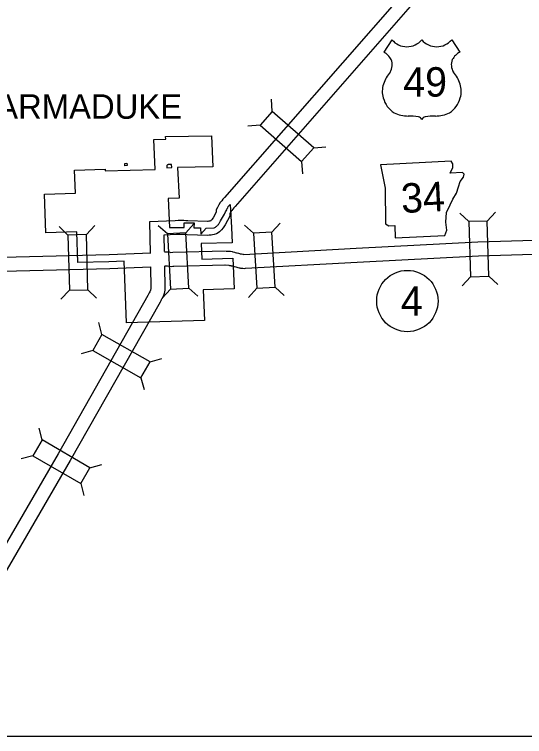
# Model space of a CAD drawing. Extents: x -0.3 to 2.65, y 0 to 1.9.
# Drawn here: x 0.1244 to 0.2273, y 0.5417 to 0.6874 of the extents above; entities that cross this region are included whole.
import ezdxf

# ---------------------------------------------------------------- set-up
doc = ezdxf.new("R2010")
doc.units = 0
for name, color, linetype in [('DSN_DRFT_DNC', 7, 'Continuous'), ('Level 21', 7, 'Continuous'), ('Level 22', 7, 'Continuous'), ('Level 26', 7, 'Continuous'), ('Level 27', 7, 'Continuous'), ('Level 38', 7, 'Continuous'), ('Level 59', 7, 'Continuous'), ('Level 6', 7, 'Continuous')]:
    doc.layers.add(name, color=color, linetype=linetype)

msp = doc.modelspace()

# ---------------------------------------------------------------- linework, layer by layer
at = {"layer": 'DSN_DRFT_DNC'}
msp.add_lwpolyline([(0.04166666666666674, 0.8750000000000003), (0.34166666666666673, 0.8750000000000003), (0.34166666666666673, 0.541666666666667), (0.04166666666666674, 0.541666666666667)], close=True, dxfattribs=at)
at = {"layer": 'Level 21'}
for points in [[(0.1670024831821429, 0.6396367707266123), (0.1679387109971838, 0.6395748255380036), (0.1683632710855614, 0.6395042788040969), (0.16837343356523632, 0.6395004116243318), (0.1687499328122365, 0.6393951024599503), (0.16893071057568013, 0.6393642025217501), (0.169170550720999, 0.6392932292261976), (0.16935035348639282, 0.6392487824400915), (0.16958915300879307, 0.6391819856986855), (0.16977474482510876, 0.6391246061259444), (0.16989319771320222, 0.6390960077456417), (0.1699938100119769, 0.639071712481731), (0.17021008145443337, 0.6390394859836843), (0.17044614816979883, 0.6389896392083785), (0.17054480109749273, 0.6389666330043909), (0.1706456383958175, 0.6389505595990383), (0.1706730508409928, 0.638947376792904), (0.1933438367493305, 0.6402108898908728), (0.21786572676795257, 0.6414539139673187), (0.22926085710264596, 0.6417985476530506)], [(0.15464540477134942, 0.6394811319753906), (0.15497090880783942, 0.6394587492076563), (0.1555985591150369, 0.6394402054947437), (0.15593432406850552, 0.6393627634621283), (0.1563514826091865, 0.6394126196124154), (0.16687934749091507, 0.6396395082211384)], [(0.09222026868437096, 0.6374214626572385), (0.09323654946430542, 0.6374956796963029), (0.09370798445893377, 0.6375075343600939), (0.0946621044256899, 0.6374841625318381), (0.0956582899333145, 0.637500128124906), (0.09666676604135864, 0.6375254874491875), (0.09792934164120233, 0.6375185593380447), (0.09863089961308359, 0.6375022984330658), (0.09898589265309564, 0.6375394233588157), (0.0994311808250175, 0.637529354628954), (0.10086031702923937, 0.637574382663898), (0.1060599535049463, 0.6378364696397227), (0.10886551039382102, 0.6379921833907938), (0.11137386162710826, 0.6380646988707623), (0.11226629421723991, 0.6381060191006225), (0.11516358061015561, 0.6381788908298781), (0.1185378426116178, 0.6382825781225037), (0.12474545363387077, 0.6384292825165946), (0.14352280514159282, 0.6389109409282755), (0.15190330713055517, 0.6392507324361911)], [(0.16681681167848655, 0.6368304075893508), (0.1676145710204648, 0.6367776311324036), (0.1676252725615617, 0.6367758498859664), (0.16779748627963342, 0.6367103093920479), (0.16801254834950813, 0.6366809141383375), (0.16813257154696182, 0.6366473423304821), (0.1682925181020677, 0.6366200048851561), (0.168433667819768, 0.6365782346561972), (0.16863390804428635, 0.6365287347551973), (0.16879482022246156, 0.6364837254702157), (0.16902859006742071, 0.6364114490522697), (0.16923308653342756, 0.6363620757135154), (0.16945542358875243, 0.636308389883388), (0.16971185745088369, 0.6362701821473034), (0.16983617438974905, 0.636243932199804), (0.17000336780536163, 0.636204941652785), (0.17026197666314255, 0.636163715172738), (0.17044316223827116, 0.6361426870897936), (0.17078795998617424, 0.6361216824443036), (0.17098140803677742, 0.6361477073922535), (0.19349328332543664, 0.6374023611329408), (0.21797944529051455, 0.6386435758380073), (0.2291270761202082, 0.6389807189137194)], [(0.154805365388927, 0.636650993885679), (0.15483285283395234, 0.636649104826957), (0.15523748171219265, 0.6366371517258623), (0.15555701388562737, 0.6365634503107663), (0.15597577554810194, 0.6365215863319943), (0.15634341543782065, 0.6365791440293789), (0.1565491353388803, 0.6366037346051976), (0.16693994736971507, 0.6368276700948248)], [(0.09242511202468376, 0.6346164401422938), (0.09337440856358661, 0.6346857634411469), (0.09370890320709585, 0.6346941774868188), (0.09465018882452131, 0.6346711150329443), (0.0957161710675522, 0.6346881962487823), (0.09669441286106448, 0.6347127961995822), (0.09788903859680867, 0.6347062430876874), (0.09874504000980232, 0.6346864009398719), (0.0991008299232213, 0.6347236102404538), (0.09944368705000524, 0.6347158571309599), (0.10097540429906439, 0.6347641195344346), (0.10620867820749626, 0.635027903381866), (0.10898409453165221, 0.6351819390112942), (0.11147954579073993, 0.6352540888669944), (0.11236670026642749, 0.6352951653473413), (0.11524213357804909, 0.635367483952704), (0.11861425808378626, 0.6354711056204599), (0.12481473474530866, 0.6356176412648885), (0.14361584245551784, 0.6360999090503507), (0.15181693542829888, 0.6364324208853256)]]:
    msp.add_lwpolyline(points, dxfattribs=at)
at = {"layer": 'Level 22'}
msp.add_lwpolyline([(0.19825524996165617, 0.6570456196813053), (0.19920751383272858, 0.6523294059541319), (0.1992538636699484, 0.6451060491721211), (0.19990743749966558, 0.6447419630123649), (0.20109547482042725, 0.6448018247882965), (0.20122317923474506, 0.6422673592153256), (0.2112026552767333, 0.6427701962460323), (0.21162598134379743, 0.6438237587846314), (0.21138376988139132, 0.6454790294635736), (0.2115255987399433, 0.6473918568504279), (0.21232100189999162, 0.6489405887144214), (0.21281954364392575, 0.6500773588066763), (0.21355170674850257, 0.6513053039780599), (0.2139630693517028, 0.6525964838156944), (0.21430720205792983, 0.653646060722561), (0.21497612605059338, 0.6545532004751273), (0.2151065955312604, 0.655115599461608), (0.21476983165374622, 0.6554956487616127), (0.21231455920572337, 0.6553719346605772), (0.21281310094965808, 0.6565087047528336), (0.21285638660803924, 0.6572255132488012), (0.21250034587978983, 0.6577563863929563)], close=True, dxfattribs=at)
at = {"layer": 'Level 26'}
for p, q in [((0.20053087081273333, 0.6822602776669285), (0.1989082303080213, 0.6797508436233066)), ((0.21259559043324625, 0.6822602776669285), (0.21421823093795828, 0.6797508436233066))]:
    msp.add_line(p, q, dxfattribs=at)
for centre, radius, start, end in [((0.20355271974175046, 0.6848026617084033), 0.0039490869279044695, 220.0750416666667, 319.6701166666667), ((0.20957374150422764, 0.6848026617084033), 0.003949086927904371, 220.32988333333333, 319.92495833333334), ((0.1967879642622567, 0.6761079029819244), 0.00421571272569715, 30.780902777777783, 59.98827222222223), ((0.2163384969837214, 0.6761079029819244), 0.00421571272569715, 120.01172777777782, 149.21909722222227), ((0.19771559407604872, 0.6772197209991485), 0.002889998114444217, 328.8104583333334, 21.210766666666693), ((0.21541086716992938, 0.6772197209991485), 0.0028899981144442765, 158.78923333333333, 211.18954166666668), ((0.20527285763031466, 0.6712959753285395), 0.006742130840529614, 138.9564777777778, 162.69134722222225), ((0.20785360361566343, 0.6712959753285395), 0.006742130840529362, 17.308652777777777, 41.04352222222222), ((0.20304719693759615, 0.6718483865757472), 0.004454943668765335, 160.95764444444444, 197.38185555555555), ((0.21007926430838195, 0.6718483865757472), 0.004454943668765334, 342.61814444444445, 19.042355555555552), ((0.20377237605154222, 0.6718610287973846), 0.005154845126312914, 195.10743055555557, 237.13119444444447), ((0.20935408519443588, 0.6718610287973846), 0.005154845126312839, 302.8688055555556, 344.89256944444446), ((0.20386841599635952, 0.6734845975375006), 0.00661920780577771, 244.07708333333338, 269.5778527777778), ((0.20925804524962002, 0.6734845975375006), 0.0066192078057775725, 270.42214722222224, 295.92291666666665), ((0.20402149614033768, 0.6547423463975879), 0.01212490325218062, 81.19415555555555, 90.953875), ((0.20553769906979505, 0.665613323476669), 0.0011618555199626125, 28.034222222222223, 72.98637222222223), ((0.20758876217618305, 0.665613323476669), 0.0011618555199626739, 107.01362777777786, 151.96577777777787), ((0.20910496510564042, 0.6547423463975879), 0.012124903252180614, 89.04612500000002, 98.80584444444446)]:
    msp.add_arc(centre, radius, start, end, dxfattribs=at)
at = {"layer": 'Level 27'}
for points in [[(0.23887062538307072, 0.7330997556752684), (0.21717789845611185, 0.7082877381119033), (0.2162002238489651, 0.7070598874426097), (0.215723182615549, 0.7064492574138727), (0.21556655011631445, 0.7062432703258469), (0.21533925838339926, 0.7059993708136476), (0.21507742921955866, 0.7057086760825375), (0.2147759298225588, 0.7053534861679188), (0.21434821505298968, 0.7048591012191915), (0.16674346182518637, 0.6504592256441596), (0.1664469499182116, 0.6500967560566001), (0.16619319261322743, 0.6497620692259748), (0.16608823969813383, 0.6496233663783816), (0.16590203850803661, 0.6494166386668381), (0.1656448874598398, 0.6489837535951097), (0.16548952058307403, 0.648699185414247), (0.1653403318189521, 0.6484147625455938), (0.1650963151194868, 0.6479254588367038), (0.16506586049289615, 0.6474507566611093)], [(0.23901848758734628, 0.7289958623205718), (0.21933782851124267, 0.7064852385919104), (0.21840854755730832, 0.7053181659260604), (0.21795083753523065, 0.7047322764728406), (0.2177200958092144, 0.7044288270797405), (0.21741306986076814, 0.7040993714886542), (0.217194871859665, 0.7038571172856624), (0.21691155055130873, 0.7035233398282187), (0.21646997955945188, 0.7030129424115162), (0.16889076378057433, 0.6486422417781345), (0.16865672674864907, 0.6483561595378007), (0.16843516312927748, 0.648063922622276), (0.16825847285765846, 0.6478304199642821), (0.1681779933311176, 0.6477410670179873), (0.16808897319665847, 0.6475912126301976), (0.1679692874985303, 0.6473719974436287), (0.1678665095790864, 0.6471760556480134), (0.16783376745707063, 0.6466657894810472)], [(0.16506586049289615, 0.6474507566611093), (0.1644802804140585, 0.6463491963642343), (0.16423550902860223, 0.6459817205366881), (0.1641508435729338, 0.6458800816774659), (0.16402618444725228, 0.6457692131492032), (0.16392233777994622, 0.6456660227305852), (0.1637826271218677, 0.6456561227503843), (0.16358095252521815, 0.6456296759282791), (0.16337696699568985, 0.6456081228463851), (0.163322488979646, 0.6456033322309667), (0.1593639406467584, 0.6457242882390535), (0.15898578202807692, 0.6457425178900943), (0.15853684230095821, 0.645760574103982), (0.15810620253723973, 0.6457708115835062), (0.15787323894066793, 0.6457649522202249), (0.15743437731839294, 0.6458232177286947), (0.15682457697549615, 0.6457370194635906), (0.1516013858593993, 0.6455049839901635), (0.15179049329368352, 0.6392043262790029)], [(0.16783376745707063, 0.6466657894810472), (0.16689828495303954, 0.6449060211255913), (0.16649282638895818, 0.644297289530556), (0.16617716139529, 0.6439183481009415), (0.16595339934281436, 0.6437193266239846), (0.165749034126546, 0.6435162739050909), (0.16548398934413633, 0.643323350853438), (0.1651253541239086, 0.643090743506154), (0.16468644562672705, 0.6429528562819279), (0.1643298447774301, 0.6428753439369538), (0.16406509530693, 0.642856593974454), (0.16391161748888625, 0.6428364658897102), (0.1636480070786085, 0.6428086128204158), (0.16340307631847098, 0.6427870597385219), (0.15925328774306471, 0.6429138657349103), (0.1588615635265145, 0.6429327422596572), (0.1584468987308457, 0.6429494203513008), (0.15810813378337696, 0.6429574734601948), (0.15772258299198, 0.6429477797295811), (0.15744634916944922, 0.6429844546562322), (0.1570844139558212, 0.6429332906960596), (0.15449578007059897, 0.6428182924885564), (0.15459381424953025, 0.6395518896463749)], [(0.15185350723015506, 0.636432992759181), (0.1519197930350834, 0.6322032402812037), (0.15190398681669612, 0.6319493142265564), (0.15185299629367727, 0.63181853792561), (0.15181118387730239, 0.6316880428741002), (0.1517705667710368, 0.6316060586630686), (0.1517104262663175, 0.6314772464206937), (0.15166946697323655, 0.6313960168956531), (0.1515695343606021, 0.6312151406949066), (0.1514975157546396, 0.6310608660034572), (0.151412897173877, 0.6309169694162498), (0.1512834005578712, 0.6306498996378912), (0.13318327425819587, 0.5987435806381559), (0.10002593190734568, 0.5416666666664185)], [(0.1546629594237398, 0.6366487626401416), (0.15473365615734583, 0.6321378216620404), (0.15470957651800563, 0.6317509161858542), (0.1546824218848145, 0.6314078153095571), (0.15457908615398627, 0.6310680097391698), (0.15450487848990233, 0.6308777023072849), (0.15442510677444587, 0.6306287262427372), (0.15430520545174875, 0.6303867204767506), (0.1542408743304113, 0.6302489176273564), (0.15415687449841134, 0.6300823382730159), (0.15407754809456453, 0.6299387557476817), (0.15398953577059, 0.629750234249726), (0.15389441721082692, 0.629588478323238), (0.15377448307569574, 0.6293411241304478), (0.13562243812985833, 0.5973432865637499), (0.10327855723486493, 0.5416666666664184)]]:
    msp.add_lwpolyline(points, dxfattribs=at)
at = {"layer": 'Level 38'}
for p, q in [((0.1763807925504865, 0.667792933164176), (0.17621628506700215, 0.6702624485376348)), ((0.17393595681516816, 0.6649991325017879), (0.17146644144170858, 0.6648346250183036)), ((0.18476220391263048, 0.6604584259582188), (0.18723171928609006, 0.6606229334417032)), ((0.18231736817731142, 0.6576646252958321), (0.18248187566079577, 0.6551951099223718)), ((0.21605880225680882, 0.6455636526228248), (0.21425661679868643, 0.6472600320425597)), ((0.21976959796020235, 0.64567588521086), (0.22146597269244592, 0.647478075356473)), ((0.13517973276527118, 0.642860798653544), (0.13338534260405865, 0.6445654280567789)), ((0.13889100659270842, 0.6429560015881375), (0.14059564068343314, 0.6447503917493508)), ((0.15523821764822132, 0.6430669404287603), (0.15339345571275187, 0.6447169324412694)), ((0.1589449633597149, 0.643273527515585), (0.1605949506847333, 0.6451182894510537)), ((0.17263397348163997, 0.643225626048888), (0.17078921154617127, 0.644875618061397)), ((0.17634071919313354, 0.6434322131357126), (0.177990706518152, 0.6452769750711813)), ((0.21639549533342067, 0.634431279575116), (0.2146991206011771, 0.632629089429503)), ((0.22010629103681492, 0.6345435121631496), (0.2219084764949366, 0.6328471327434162)), ((0.13546534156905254, 0.631726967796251), (0.13376070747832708, 0.6299325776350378)), ((0.1391766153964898, 0.6318221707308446), (0.14097100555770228, 0.6301175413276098)), ((0.1558579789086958, 0.6319467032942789), (0.15420799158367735, 0.6301019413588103)), ((0.15956472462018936, 0.6321532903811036), (0.1614094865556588, 0.6305032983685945)), ((0.17325373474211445, 0.6321053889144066), (0.171603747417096, 0.6302606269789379)), ((0.17696048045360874, 0.6323119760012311), (0.17880524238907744, 0.6306619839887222)), ((0.14204578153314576, 0.6228020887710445), (0.14138710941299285, 0.6251878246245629)), ((0.14021394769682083, 0.6195729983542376), (0.1378282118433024, 0.6189143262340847)), ((0.15173305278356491, 0.6173065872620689), (0.15411878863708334, 0.6179652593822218)), ((0.14990121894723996, 0.6140774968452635), (0.15055989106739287, 0.6116917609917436)), ((0.1299785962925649, 0.6015136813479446), (0.12934441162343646, 0.6039060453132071)), ((0.1281137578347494, 0.5983035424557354), (0.1257213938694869, 0.5976693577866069)), ((0.13960902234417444, 0.5959191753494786), (0.14200138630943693, 0.596553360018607)), ((0.1377441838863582, 0.5927090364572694), (0.13837836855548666, 0.5903166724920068))]:
    msp.add_line(p, q, dxfattribs=at)
for points in [[(0.18476220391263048, 0.6604584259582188), (0.1763807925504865, 0.667792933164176), (0.17393595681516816, 0.6649991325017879), (0.18231736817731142, 0.6576646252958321)], [(0.22010629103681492, 0.6345435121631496), (0.21976959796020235, 0.64567588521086), (0.21605880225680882, 0.6455636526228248), (0.21639549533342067, 0.634431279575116)], [(0.13517973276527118, 0.642860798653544), (0.13546534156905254, 0.631726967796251), (0.1391766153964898, 0.6318221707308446), (0.13889100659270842, 0.6429560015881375)], [(0.15956472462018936, 0.6321532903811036), (0.1589449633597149, 0.643273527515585), (0.15523821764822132, 0.6430669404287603), (0.1558579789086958, 0.6319467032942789)], [(0.17696048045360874, 0.6323119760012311), (0.17634071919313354, 0.6434322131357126), (0.17263397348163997, 0.643225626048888), (0.17325373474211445, 0.6321053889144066)], [(0.14021394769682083, 0.6195729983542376), (0.14990121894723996, 0.6140774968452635), (0.15173305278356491, 0.6173065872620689), (0.14204578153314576, 0.6228020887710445)], [(0.1281137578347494, 0.5983035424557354), (0.1377441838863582, 0.5927090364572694), (0.13960902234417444, 0.5959191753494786), (0.1299785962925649, 0.6015136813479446)]]:
    msp.add_lwpolyline(points, close=True, dxfattribs=at)
at = {"layer": 'Level 59'}
msp.add_circle((0.20365004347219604, 0.6295424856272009), 0.006187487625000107, dxfattribs=at)
at = {"layer": 'Level 6'}
for points in [[(0.1469990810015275, 0.6251665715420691), (0.14654465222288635, 0.6375727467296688), (0.14340833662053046, 0.637484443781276), (0.1371825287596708, 0.6373194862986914), (0.13695909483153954, 0.6434937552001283), (0.1307438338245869, 0.6433196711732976), (0.13047525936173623, 0.6510891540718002), (0.1366772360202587, 0.6512825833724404), (0.13650869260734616, 0.6559400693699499), (0.1427029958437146, 0.6561398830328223), (0.1427159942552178, 0.655796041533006), (0.15279928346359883, 0.6560951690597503), (0.1525364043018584, 0.6621545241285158), (0.15489584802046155, 0.6622313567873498), (0.15487416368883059, 0.6627311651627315), (0.15489043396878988, 0.6627316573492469), (0.16411179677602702, 0.6628525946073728), (0.16439975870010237, 0.6566423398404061), (0.1573082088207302, 0.6564781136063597), (0.15759419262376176, 0.6503105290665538), (0.15541512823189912, 0.6502619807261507), (0.15567078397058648, 0.644369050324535), (0.1567380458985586, 0.6443949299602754), (0.15742355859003, 0.6443986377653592), (0.1578033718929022, 0.6443986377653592), (0.1586280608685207, 0.644374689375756), (0.15864883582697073, 0.6453412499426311), (0.16061711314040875, 0.6452981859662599), (0.1605963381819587, 0.6443316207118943), (0.16192145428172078, 0.6443123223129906), (0.16198030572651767, 0.643043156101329), (0.16303340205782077, 0.6442592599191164), (0.1646939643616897, 0.6442932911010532), (0.164831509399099, 0.6443824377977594), (0.16496210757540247, 0.6444755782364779), (0.16508854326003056, 0.6445728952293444), (0.16520386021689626, 0.6446674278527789), (0.16530528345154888, 0.6447564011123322), (0.16537613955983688, 0.6448217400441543), (0.16545950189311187, 0.6449037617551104), (0.16554842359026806, 0.6449982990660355), (0.1656165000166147, 0.6450997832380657), (0.16570958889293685, 0.6452513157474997), (0.16576933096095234, 0.6453472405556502), (0.16597912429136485, 0.6457517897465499), (0.16673493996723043, 0.6470551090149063), (0.16699058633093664, 0.6475305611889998), (0.16720176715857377, 0.6479392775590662), (0.16732403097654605, 0.6481895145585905), (0.16741017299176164, 0.6483785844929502), (0.16752410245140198, 0.6486260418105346), (0.16758245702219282, 0.6487066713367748), (0.16763803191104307, 0.6487650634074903), (0.16793566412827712, 0.6490179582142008), (0.16816681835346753, 0.6443644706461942), (0.16832030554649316, 0.6412745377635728), (0.16206857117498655, 0.6411396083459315), (0.16221350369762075, 0.6380139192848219), (0.16847351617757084, 0.638190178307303), (0.16873934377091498, 0.6320035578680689), (0.16246448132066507, 0.6318224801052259), (0.16271544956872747, 0.6256311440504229)], [(0.14664133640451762, 0.6568478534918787), (0.14662231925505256, 0.6573162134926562), (0.1470909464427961, 0.6573270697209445), (0.14710995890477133, 0.656858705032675)], [(0.15514761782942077, 0.656428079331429), (0.15614035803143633, 0.6564510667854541), (0.15605092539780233, 0.6570888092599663), (0.15601302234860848, 0.6570820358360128), (0.1559246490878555, 0.657074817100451), (0.15565414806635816, 0.6570687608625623), (0.15550101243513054, 0.6570679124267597), (0.15542050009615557, 0.6570658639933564), (0.15537506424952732, 0.6570605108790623), (0.1553376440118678, 0.6570515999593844), (0.15529488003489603, 0.6570293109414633), (0.1552574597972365, 0.6570052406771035), (0.15512639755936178, 0.6569172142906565)]]:
    msp.add_lwpolyline(points, close=True, dxfattribs=at)

# ---------------------------------------------------------------- texts
at = {"layer": 'Level 22'}
msp.add_text('34', height=0.00593998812, rotation=2.8845296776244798, dxfattribs=at).set_placement((0.20251368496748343, 0.6472856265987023))
at = {"layer": 'Level 26'}
msp.add_text('49', height=0.005939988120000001, dxfattribs=at).set_placement((0.2028249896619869, 0.6707814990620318))
at = {"layer": 'Level 59'}
msp.add_text('4', height=0.005939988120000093, dxfattribs=at).set_placement((0.2023213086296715, 0.6265724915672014))
at = {"layer": 'Level 6'}
msp.add_text('MARMADUKE', height=0.004949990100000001, dxfattribs=at).set_placement((0.11518922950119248, 0.6663123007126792))

doc.saveas('drawing.dxf')
